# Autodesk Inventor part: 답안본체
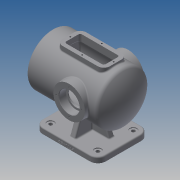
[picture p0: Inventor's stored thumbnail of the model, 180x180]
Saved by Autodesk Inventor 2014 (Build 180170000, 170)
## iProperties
Created: 2021-11
Part Number: 답안본체
Material: Generic
Document SubType Name: Modeling
Designer: kb542
Density: 1 g/cm^3
Appearance: Default
Author: kb542
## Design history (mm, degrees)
sketch "스케치1"
  geometry: L1 (0, 0)-(210, 0); L2 (13, 65)-(181.239, 65); L3 (10, 62)-(10, 47.5); L4 (10, 47.5)-(0, 47.5); L5 (0, 47.5)-(0, 32.5); L6 (0, 32.5)-(25, 32.5); L7 (25, 32.5)-(25, 52); L8 (28, 55)-(179.75, 55); A1 r 100 centre (110, 0) between (210, 0) and (189.154, 61.111); A2 r 90 centre (110, 0) between (200, 0) and (182.155, 53.793); A3 r 10 centre (181.239, 55) between (189.154, 61.111) and (181.239, 65); A4 r 3 centre (179.75, 52) between (182.155, 53.793) and (179.75, 55); A5 r 3 centre (28, 52) between (28, 55) and (25, 52); A6 r 3 centre (13, 62) between (13, 65) and (10, 62); 2 further points
  constraints: 16 end point, 14 point on circle, 8 tangent, 6 centre point, 5 parallel, 4 point on line, 2 perpendicular, 1 concentric, 1 equal radius, 1 horizontal, 1 vertical alignment
  dimensions: "d0" = 210 distance of L1.start L1.end; "d1" = 100 radius of A1; "d2" = 10 distance between parallel lines of L2 L8; "d3" = 10 radial gap between concentric circles of A1 A2; "d4" = 130 diameter of L2 L1; "d5" = 65 diameter of L6 L1; "d6" = 95 diameter of L4 L1; "d7" = 10 distance between parallel lines of L3 L5; "d8" = 10 radius of A3; "d9" = 3 radius of A4; "d10" = 3 radius of A5; "d11" = 25 distance of L5.end L6.end
revolve "회전1" sketch "스케치1" stored, may be unused: angle "d12" = 90 deg
node "작업 평면1"
sketch "스케치2"
  geometry: L1 (50, 65)-(170, 65); L2 (190, 45)-(190, -45); L3 (170, -65)-(50, -65); L4 (30, -45)-(30, 45); L5 (181.239, -65)-(181.239, 65) reference; L6 (13, -65)-(13, 65) reference; L7 (10, -47.5)-(10, 47.5) reference; L8 (0, -47.5)-(0, 47.5) reference; A1 r 20 centre (170, 45) between (190, 45) and (170, 65); A2 r 20 centre (170, -45) between (170, -65) and (190, -45); A3 r 20 centre (50, -45) between (30, -45) and (50, -65); A4 r 20 centre (50, 45) between (50, 65) and (30, 45); 6 further points
  constraints: 8 end point, 8 point on circle, 8 tangent, 6 point on line, 4 centre point, 3 equal radius, 2 midpoint, 2 parallel, 1 horizontal, 1 horizontal alignment, 1 perpendicular
  dimensions: "d14" = 160 distance of point (30, 65) point (190, 65); "d15" = 30 distance between parallel lines of L4 L8; "d16" = 130 distance of point (190, 65) point (190, -65); "d17" = 20 radius of A1
extrude "돌출1" join sketch "스케치2" distance "d18" = 14; taper "d19" = 0 deg
sketch "스케치3"
  geometry: C1 r 9 at (50, 45); C2 r 9 at (50, -45); C3 r 9 at (170, -45); C4 r 9 at (170, 45); A1 r 20 centre (170, 45) between (190, 45) and (170, 65) reference; A2 r 20 centre (50, 45) between (50, 65) and (30, 45) reference; A3 r 20 centre (50, -45) between (30, -45) and (50, -65) reference; A4 r 20 centre (170, -45) between (170, -65) and (190, -45) reference; 1 further point
  constraints: 4 centre point, 3 coincident, 3 equal radius, 1 concentric, 1 horizontal alignment
  dimensions: "d20" = 18 diameter of C2
hole "구멍1" sketch "스케치3" at (50, -45), (170, -45), (50, 45), (170, 45) diameter "d21" = 9; stored, may be unused: countersink angle "d25" = 90 deg, drill point angle "d27" = 118 deg; dims "d22" = 6, "d23" = 18, "d24" = 2, "d26" = 8
sketch "스케치4"
  geometry: L1 (170, 65)-(50, 65) reference; L2 (30, 45)-(30, -45) reference; L3 (103, 7)-(117, 7); L4 (117, 7)-(117, -7); L5 (117, -7)-(103, -7); L6 (103, -7)-(103, 7); 1 further point
  constraints: 8 end point, 2 parallel, 1 horizontal, 1 perpendicular
  dimensions: "d28" = 14 distance of L3.start L3.end; "d29" = 14 distance of L5.end L3.start; "d30" = 73 distance between parallel lines of L6 L2; "d31" = 58 distance between parallel lines of L1 L3
extrude "돌출2" join sketch "스케치4" stored distance "d32" = 14; taper "d33" = 0 deg
sketch "스케치5"
  geometry: L1 (-147.123, -64.622)-(-160, -100); L2 (-170, -114)-(-50, -114) reference; L3 (-170, -114)-(-170, -100) reference; L4 (-50, -100)-(-170, -100) reference; L5 (-50, -114)-(-50, -100) reference; L6 (-110, -114)-(-110, -64.622); L7 (-170, -100)-(-190, -100) reference; L8 (-179.75, 55)-(-179.75, -55) reference; L9 (-28, 55)-(-28, -55) reference; L10 (-13, 65)-(-13, -65) reference; L11 (-181.239, 65)-(-181.239, -65) reference; L12 (-117, -64.622)-(-117, -64.622) reference; L13 (-117, -64.622)-(-103, -64.622) reference; L14 (-103, -64.622)-(-103, -64.622) reference; L15 (-103, -64.622)-(-117, -64.622) reference; 2 further points
  constraints: 4 end point, 3 midpoint, 1 horizontal alignment, 1 parallel, 1 point on line
  dimensions: "d34" = 100 diameter of L1.end L6; "d35" = 110 deg angle of L7 L1
feature "리브1" sketch "스케치5" dims "d37" = 1, "d38" = 14, "d39" = 0, "d40" = 0, "d41" = 1, "d42" = 1
node "작업 평면2"
sketch "스케치6"
  geometry: L1 (14, 95)-(58.485, 78.809); L2 (14, 90)-(14, 110) reference; L3 (0, 90)-(0, 0) reference; L4 (0, 90)-(14, 90) reference; L5 (14, 0)-(14, 90) reference; L6 (0, 0)-(14, 0) reference; L7 (0, 45)-(114, 45); C1 r 61.111 at (114, 45) reference; 1 further point
  constraints: 4 end point, 1 midpoint, 1 parallel, 1 point on line, 2 other
  dimensions: "d43" = 110 deg angle of L2 L1; "d44" = 100 diameter of L1.start L7
feature "리브2" sketch "스케치6" dims "d45" = 1, "d46" = 14, "d47" = 0, "d48" = 0, "d49" = 1, "d50" = 1
node "작업 평면3"
node "작업 평면4"
sketch "스케치8"
  geometry: L1 (65, 30)-(155, 30); L2 (170, 15)-(170, -15); L3 (155, -30)-(65, -30); L4 (50, -15)-(50, 15); A1 r 15 centre (65, -15) between (50, -15) and (65, -30); A2 r 15 centre (155, -15) between (155, -30) and (170, -15); A3 r 15 centre (155, 15) between (170, 15) and (155, 30); A4 r 15 centre (65, 15) between (65, 30) and (50, 15); 2 further points
  constraints: 8 end point, 8 point on circle, 8 tangent, 4 centre point, 3 equal radius, 2 parallel, 1 horizontal, 1 horizontal alignment, 1 midpoint, 1 perpendicular
  dimensions: "d62" = 15 radius of A1; "d63" = 120 distance between parallel lines of L2 L4; "d64" = 50 distance from line of point (0, 0) L4; "d65" = 60 distance between parallel lines of L3 L1
extrude "돌출3" join sketch "스케치8" stored distance "d66" = 14; taper "d67" = 0 deg
sketch "스케치9"
  geometry: L1 (65, -30)-(155, -30) reference; L2 (170, -15)-(170, 15) reference; L3 (155, 30)-(65, 30) reference; L4 (50, 15)-(50, -15) reference; L5 (160, 15)-(160, -15); L6 (155, -20)-(65, -20); L7 (60, -15)-(60, 15); L8 (65, 20)-(155, 20); A1 r 15 centre (155, -15) between (155, -30) and (170, -15) reference; A2 r 15 centre (155, 15) between (170, 15) and (155, 30) reference; A3 r 15 centre (65, 15) between (65, 30) and (50, 15) reference; A4 r 15 centre (65, -15) between (50, -15) and (65, -30) reference; A5 r 5 centre (155, 15) between (160, 15) and (155, 20); A6 r 5 centre (155, -15) between (155, -20) and (160, -15); A7 r 5 centre (65, -15) between (60, -15) and (65, -20); A8 r 5 centre (65, 15) between (65, 20) and (60, 15); 1 further point
  constraints: 8 end point, 8 point on circle, 4 centre point, 7 other
  dimensions: "d68" = 10 distance between parallel lines of L2 L5
extrude "돌출4" cut sketch "스케치9" stored distance "d69" = 14; taper "d70" = 0 deg
sketch "스케치10"
  geometry: C1 r 40 at (-127, 0); 1 further point
  constraints: 1 centre point, 1 horizontal alignment
  dimensions: "d71" = 80 diameter of C1; "d72" = 127 distance of point (0, 0) C1.centre
extrude "돌출5" join sketch "스케치10" stored distance "d73" = 14; taper "d74" = 0 deg
hole "구멍2" diameter "d77" = 42; stored, may be unused: countersink angle "d81" = 90 deg, drill point angle "d83" = 118 deg; dims "d75" = 10, "d76" = 10, "d78" = 6, "d79" = 52, "d80" = 18, "d82" = 8
sketch "스케치11"
  geometry: L1 (120, 0)-(0, 0) reference; L2 (34.543, 8.002)-(85.457, 8.002); L3 (85.457, 8.002)-(85.457, 1.998); L4 (85.457, 1.998)-(34.543, 1.998); L5 (34.543, 1.998)-(34.543, 8.002); L6 (53, 58.485)-(67, 58.485) reference; 4 further points
  constraints: 3 midpoint, 1 vertical alignment, 2 other
  dimensions: "d84" = 5 distance from line of L1 point (34.543, 5)
feature "엠보싱1" sketch "스케치11" dims "d0" = 210, "d1" = 100, "d2" = 10, "d3" = 10, "d4" = 130, "d5" = 65, "d6" = 95, "d7" = 10, "d8" = 10, "d9" = 3, "d10" = 3, "d11" = 25, "d85" = 0.5, "d86" = 0
fillet "모깎기1" dims "d87" = 3
fillet "모깎기2" dims "d88" = 3
fillet "모깎기3" dims "d89" = 3
sketch "스케치12" dims "d90" = 80
  geometry: C1 r 32.5 at (0, 0) reference; C2 r 47.5 at (0, 0) reference; 2 further points
  constraints: 2 vertical alignment, 1 coincident, 2 other
hole "구멍3" sketch "스케치12" at (0, 40) diameter "d91" = 3.459; stored, may be unused: countersink angle "d95" = 90 deg, drill point angle "d97" = 118 deg; dims "d92" = 11, "d93" = 52, "d94" = 18, "d96" = 13
sketch "스케치13" dims "d101" = 65
  geometry: C1 r 26 at (0, 0) reference; C2 r 40 at (0, 0) reference; 3 further points
  constraints: 2 vertical alignment, 1 coincident, 2 other
hole "구멍4" sketch "스케치13" at (0, 32.5) diameter "d102" = 3.459; stored, may be unused: countersink angle "d106" = 90 deg, drill point angle "d108" = 118 deg; dims "d103" = 11, "d104" = 52, "d105" = 18, "d107" = 13
chamfer "모따기1" distance "d112" = 1; stored, may be unused: second distance "d113" = 2, angle "d114" = 45 deg
fillet "모깎기4" dims "d115" = 0.3
sketch "스케치14"
  geometry: L1 (170, -15)-(170, 15) reference; L2 (155, 30)-(65, 30) reference; L3 (50, 15)-(50, -15) reference; L4 (110, 25)-(110, -25); 8 further points
  constraints: 5 midpoint, 3 horizontal alignment, 2 end point, 2 vertical alignment, 1 parallel
  dimensions: "d116" = 55 horizontal distance of L4.start point (55, 0); "d117" = 55 horizontal distance of L4.start point (165, 0); "d118" = 50 distance of L4.start L4.end
hole "구멍5" sketch "스케치14" at (110, -25), (165, 0), (110, 25), (55, 0) diameter "d119" = 3.459; stored, may be unused: countersink angle "d123" = 90 deg, drill point angle "d125" = 118 deg; dims "d120" = 9, "d121" = 52, "d122" = 18, "d124" = 11
fillet "모깎기5" dims "d126" = 3
fillet "모깎기6" dims "d127" = 3
node "솔리드1"
mirror "대칭1"
mirror "대칭2"
mirror "대칭4"
pattern_circular "원형 패턴1" dims angle "d99" = 360 deg
pattern_circular "원형 패턴2" dims angle "d110" = 360 deg
mirror "대칭5"
node "투영된 루프1"
node "투영된 루프2"
node "투영된 루프3"
node "투영된 루프4"
node "투영된 루프5"
node "투영된 루프6"
other parameters: "d13" = -114, "d60" = 75
